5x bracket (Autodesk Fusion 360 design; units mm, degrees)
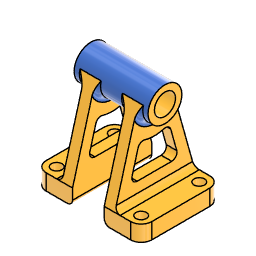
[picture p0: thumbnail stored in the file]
sketch "Sketch1" plane through (0, 0, 0) normal (1, 0, 0) x axis (0, 1, 0)
  line L1 (37.5, -75) -> (-37.5, -75)
  line L2 (37.5, -90) -> (37.5, -75)
  line L3 (-37.5, -90) -> (37.5, -90)
  line L4 (-37.5, -75) -> (-37.5, -90)
  line L5 (37.5, -90) -> (-37.5, -75)
  line L6 (-37.5, -90) -> (37.5, -75)
  line L7 (-15.4132, 4.2933) -> (-37.5, -75)
  line L8 (15.4132, 4.2933) -> (37.5, -75)
  circle C1 centre (0, 0) radius 10
  circle C2 centre (0, 0) radius 16
  point P1 (0, 0)
  point P2 (0, 0)
  point P8 (0, -82.5)
  point P3 (0, 0)
  point P9 (-15.4132, 4.2933)
  point P10 (15.4132, 4.2933)
  point P5 (37.5, -75)
  point P6 (37.5, -90)
  point P7 (-37.5, -90)
  coincident P1 P2
  concentric C1 C2
  horizontal L1
  perpendicular L1 L2
  parallel L1 L3
  parallel L2 L4
  coincident L5 P8
  coincident L6 P8
  vertical P3 P8
  coincident C2 P9
  tangent C2 L7
  coincident C2 P10
  tangent C2 L8
  dimension "d1" diameter C1 = 20
  dimension "d2" distance C1 C2 = 6
  dimension "d3" distance P5 P6 = 15
  dimension "d4" distance P6 P7 = 75
  dimension "d5" distance P3 L1 = 75
extrude "Extrude1" new body sketch "Sketch1" profile of C1 C2 L1 L2 L3 L4 L7 L8 distance 25
extrude "Extrude2" add sketch "Sketch1" profile of C1 C2 distance 35
extrude "Extrude3" add sketch "Sketch1" profile of L1 L2 L3 L4 distance 50
fillet "Fillet1" radius 10
sketch "Sketch2" plane through (0, -37.5, 0) normal (0, -1, 0) x axis (1, 0, 0)
  line L1 (-40, -90) -> (-40, -75)
  line L2 (40, -90) -> (-40, -90)
  line L3 (40, -75) -> (40, -90)
  line L4 (25, -75) -> (40, -75)
  line L5 (-25, -75) -> (25, -75)
  line L6 (-40, -75) -> (-25, -75)
  line L7 (35, 16) -> (35, -16)
  line L8 (-35, -16) -> (-35, 16)
  line L9 (25, 4.2933) -> (-25, 4.2933)
  line L10 (25, -16) -> (25, 4.2933)
  line L11 (-25, 4.2933) -> (25, 4.2933)
  line L12 (-25, 4.2933) -> (-25, -16)
  line L13 (-25, -75) -> (-25, -16)
  line L14 (25, -75) -> (25, -16)
  line L15 (15, -16) -> (-15, -16)
  line L16 (15, -75) -> (15, -16)
  line L17 (-15, -75) -> (15, -75)
  line L18 (-15, -16) -> (-15, -75)
  line L19 (-25, -90) -> (-25, -75)
  line L20 (25, -90) -> (25, -75)
  line L21 (-15, -90) -> (-15, -75)
  line L22 (15, -90) -> (15, -75)
  point P15 (-25, -16)
  point P16 (-25, -16)
  point P7 (-25, -75)
  point P17 (-25, -75)
  point P14 (25, -16)
  point P18 (25, -16)
  point P6 (25, -75)
  point P19 (25, -75)
  point P22 (15, -75)
  point P24 (-25, -90)
  point P25 (25, -90)
  point P26 (-15, -90)
  point P27 (15, -90)
  coincident P15 P16
  coincident P7 P17
  coincident P14 P18
  coincident P6 P19
  horizontal L15
  vertical L16
  horizontal L17
  vertical L18
  coincident L5 P22
  coincident P16 L15
  coincident L2 P24
  perpendicular L2 L19
  coincident L2 P25
  perpendicular L2 L20
  coincident L2 P26
  perpendicular L2 L21
  coincident L2 P27
  perpendicular L2 L22
  dimension "d14" distance L13 L18 = 10
  dimension "d15" distance L14 L16 = 10 (= "d14")
extrude "Extrude4" cut sketch "Sketch2" profile of L2 L5 L15 L16 L17 L18 L21 L22 no distance stored
sketch "Sketch3" plane through (0, 0, 0) normal (1, 0, 0) x axis (0, 1, 0)
  line L1 (37.5, -75) -> (-37.5, -75)
  line L2 (15.4132, 4.2933) -> (37.5, -75)
  line L3 (-37.5, -75) -> (-15.4132, 4.2933)
  circle C1 centre (0, 0) radius 26.4532
  arc A1 centre (0, 0) radius 16 clockwise from (15.4132, 4.2933) to (-15.4132, 4.2933)
  point P1 (0, 0)
  point P2 (0, 0)
  point P3 (21.0658, -16)
  coincident P1 P2
  coincident C1 P3
extrude "Extrude5" cut sketch "Sketch3" profile of C1 L2 A1 L3 to an object Side2Offset 0
fillet "Fillet2" radius 5
sketch "Sketch4" plane through (0, 0, -90) normal (0, 0, -1) x axis (1, 0, 0)
  line L1 (20, -37.5) -> (20, 37.5)
  line L2 (40, -37.5) -> (20, -37.5)
  line L3 (50, 27.5) -> (50, -27.5)
  line L4 (20, 37.5) -> (40, 37.5)
  line L5 (-20, 37.5) -> (-20, -37.5)
  line L6 (-40, 37.5) -> (-20, 37.5)
  line L7 (-50, -27.5) -> (-50, 27.5)
  line L8 (-20, -37.5) -> (-40, -37.5)
  arc A1 centre (40, -27.5) radius 10 clockwise from (50, -27.5) to (40, -37.5)
  arc A2 centre (40, 27.5) radius 10 clockwise from (40, 37.5) to (50, 27.5)
  arc A3 centre (-40, 27.5) radius 10 clockwise from (-50, 27.5) to (-40, 37.5)
  arc A4 centre (-40, -27.5) radius 10 clockwise from (-40, -37.5) to (-50, -27.5)
  circle C1 centre (40, 27.5) radius 5
  circle C2 centre (40, -27.5) radius 5
  circle C3 centre (-40, -27.5) radius 5
  circle C4 centre (-40, 27.5) radius 5
  concentric A2 C1
  concentric A1 C2
  concentric A4 C3
  concentric A3 C4
  equal C3 C4
  equal C2 C3
  equal C1 C2
  dimension "d23" diameter C1 = 10
extrude "Extrude6" cut sketch "Sketch4" profile of C1 C2 C3 C4 to an object
sketch "Sketch5" plane through (25, 0, 0) normal (1, 0, 0) x axis (0, 1, 0)
  line L1 (36.1073, -70) -> (-36.1073, -70)
  line L2 (19.0629, -8.8094) -> (36.1073, -70)
  line L3 (-36.1073, -70) -> (-19.0629, -8.8094)
  line L4 (13.9409, -27.6885) -> (22.9411, -60)
  line L5 (22.9411, -60) -> (-22.9411, -60)
  line L6 (-22.9411, -60) -> (-13.9409, -27.6885)
  arc A1 centre (0, 0) radius 21 clockwise from (19.0629, -8.8094) to (-19.0629, -8.8094)
  arc A2 centre (0, 0) radius 31 clockwise from (13.9409, -27.6885) to (-13.9409, -27.6885)
  dimension "d26" = -10
extrude "Extrude7" cut sketch "Sketch5" profile of L4 A2 L5 L6 no distance stored
fillet "Fillet3" radius 5
component_from_bodies "Body->Comp"
base_feature "Base Feature1"
base_feature "Base Feature1"
base_feature "Base Feature1"
base_feature "Base Feature1"
sketch "Sketch1" plane through (0, 0, 0) normal (1, 0, 0) x axis (0, 1, 0)
  line L1 (-7.5, 34.615) -> (-7.5, 19.615)
  line L2 (7.5, 34.615) -> (-7.5, 34.615)
  line L3 (7.5, 19.615) -> (7.5, 34.615)
  line L4 (-17.5, 34.615) -> (-7.5, 34.615)
  line L5 (-17.5, 44.615) -> (-17.5, 34.615)
  line L6 (17.5, 44.615) -> (-17.5, 44.615)
  line L7 (17.5, 34.615) -> (17.5, 44.615)
  line L8 (7.5, 34.615) -> (17.5, 34.615)
  circle C1 centre (0, 0) radius 16
  circle C2 centre (-7.5, 19.615) radius 5
  circle C3 centre (7.5, 19.615) radius 5
  point P3 (-7.5, 19.615)
  point P5 (-7.5, 19.615)
  point P4 (7.5, 19.615)
  point P8 (7.5, 19.615)
  point P1 (0, 0)
  point P7 (7.5, 34.615)
  point P11 (17.5, 44.615)
  point P12 (17.5, 34.615)
  equal C2 C3
  tangent C1 C3
  tangent C1 C2
  coincident P3 P5
  vertical L1
  perpendicular L1 L2
  coincident P4 P8
  perpendicular L2 L3
  perpendicular L1 L4
  perpendicular L4 L5
  perpendicular L5 L6
  perpendicular L4 L7
  perpendicular L7 L8
  equal L4 L8
  equal L4 L5
  dimension "d30" diameter C3 = 10
  dimension "d31" distance P3 P4 = 15
  dimension "d32" distance P1 P4 = 7.5 (= "d31 / 2")
  dimension "d33" distance P7 P8 = 15
  dimension "d34" distance P11 P12 = 10
extrude "Extrude1" add sketch "Sketch1" distance 1
sketch "Sketch1" plane through (0, 0, 0) normal (1, 0, 0) x axis (0, 1, 0)
  line L1 (19.0629, -8.8094) -> (36.1073, -70)
  line L2 (34.4943, -64.2094) -> (31.811, -54.5761)
  line L3 (49.1406, -60.1297) -> (34.4943, -64.2094)
  line L4 (46.4573, -50.4964) -> (49.1406, -60.1297)
  line L5 (31.811, -54.5761) -> (46.4573, -50.4964)
  line L6 (51.8239, -69.763) -> (43.774, -40.8632)
  line L7 (61.8239, -66.9775) -> (51.8239, -69.763)
  line L8 (53.774, -38.0777) -> (61.8239, -66.9775)
  line L9 (43.774, -40.8632) -> (53.774, -38.0777)
  circle C1 centre (35.6643, -53.5028) radius 4
  circle C2 centre (38.3476, -63.136) radius 4
  point P5 (34.4943, -64.2094)
  point P7 (46.4573, -50.4964)
  point P12 (35.6643, -53.5028)
  point P4 (31.811, -54.5761)
  point P13 (38.3476, -63.136)
  point P8 (43.774, -40.8632)
  point P11 (53.774, -38.0777)
  perpendicular L2 L3
  parallel L2 L4
  parallel L3 L5
  coincident L1 P5
  parallel L1 L2
  perpendicular L6 L7
  parallel L6 L8
  parallel L7 L9
  perpendicular L5 L6
  coincident P7 L6
  coincident L5 P12
  coincident P4 C1
  coincident L3 P13
  coincident P5 C2
  equal C1 C2
  dimension "d37" distance L3 L5 = 10
  dimension "d38" distance L5 L9 = 10
  dimension "d39" distance L3 L7 = 10 (= "d38")
  dimension "d40" distance P8 P11 = 10
  dimension "d56" diameter C1 = 8
extrude "Extrude1" sketch "Sketch1" blind -2.5
mirror "Mirror1" mirrorStitchTolerance 0.1
sketch "Sketch1" plane through (0, 0, 0) normal (0, 1, 0) x axis (1, 0, 0)
  line L1 (20, 90) -> (50, 90)
  line L2 (-50, 90) -> (-20, 90)
  line L3 (25, 104) -> (25, 94)
  line L4 (35, 104) -> (25, 104)
  line L5 (35, 94) -> (35, 104)
  line L6 (-25, 104) -> (-25, 94)
  line L7 (-35, 104) -> (-25, 104)
  line L8 (-35, 94) -> (-35, 104)
  line L9 (43.6078, 104) -> (35, 104)
  line L10 (43.6078, 118.3729) -> (43.6078, 104)
  line L11 (16.3922, 118.3729) -> (43.6078, 118.3729)
  line L12 (16.3922, 104) -> (16.3922, 118.3729)
  line L13 (25, 104) -> (16.3922, 104)
  line L14 (-16.3922, 104) -> (-25, 104)
  line L15 (-16.3922, 118.3729) -> (-16.3922, 104)
  line L16 (-43.6078, 118.3729) -> (-16.3922, 118.3729)
  line L17 (-43.6078, 104) -> (-43.6078, 118.3729)
  line L18 (-35, 104) -> (-43.6078, 104)
  circle C1 centre (35, 94) radius 4
  circle C2 centre (25, 94) radius 4
  circle C3 centre (-25, 94) radius 4
  circle C4 centre (-35, 94) radius 4
  point P7 (25, 94)
  point P10 (25, 94)
  point P6 (35, 94)
  point P13 (35, 94)
  point P8 (-25, 94)
  point P14 (-25, 94)
  point P9 (-35, 94)
  point P17 (-35, 94)
  point P4 (-20, 90)
  point P3 (20, 90)
  point P11 (25, 104)
  tangent L1 C1
  tangent L1 C2
  tangent L2 C4
  equal C3 C4
  equal C2 C3
  equal C1 C2
  tangent L2 C3
  coincident P7 P10
  vertical L3
  perpendicular L3 L4
  coincident P6 P13
  perpendicular L4 L5
  coincident P8 P14
  vertical L6
  perpendicular L6 L7
  coincident P9 P17
  perpendicular L7 L8
  collinear L4 L7
  perpendicular L5 L9
  perpendicular L9 L10
  perpendicular L10 L11
  perpendicular L11 L12
  perpendicular L3 L13
  perpendicular L6 L14
  perpendicular L7 L15
  perpendicular L15 L16
  perpendicular L16 L17
  perpendicular L8 L18
  equal L13 L14
  equal L9 L18
  equal L14 L18
  equal L12 L15
  dimension "d48" diameter C1 = 8
  dimension "d49" distance P6 P7 = 10
  dimension "d50" distance P8 P9 = 10
  dimension "d51" distance P4 P8 = 5
  dimension "d52" distance P3 P7 = 5
  dimension "d53" distance P10 P11 = 10
extrude "Extrude1" add sketch "Sketch1" distance 2
sketch "Sketch1" plane through (0, 0, -90) normal (0, 0, -1) x axis (1, 0, 0)
  line L1 (20, -37.5) -> (20, 37.5)
  line L2 (40, -37.5) -> (20, -37.5)
  line L3 (50, 27.5) -> (50, -27.5)
  line L4 (20, 37.5) -> (40, 37.5)
  line L5 (64, 5) -> (54, 5)
  line L6 (64, -5) -> (64, 5)
  line L7 (54, -5) -> (64, -5)
  line L8 (64, -15) -> (64, -5)
  line L9 (74, -15) -> (64, -15)
  line L10 (74, 15) -> (74, -15)
  line L11 (64, 15) -> (74, 15)
  line L12 (64, 5) -> (64, 15)
  circle C1 centre (40, 27.5) radius 5
  circle C2 centre (40, -27.5) radius 5
  arc A1 centre (40, -27.5) radius 10 clockwise from (50, -27.5) to (40, -37.5)
  arc A2 centre (40, 27.5) radius 10 clockwise from (40, 37.5) to (50, 27.5)
  circle C3 centre (54, 5) radius 4
  circle C4 centre (54, -5) radius 4
  point P10 (54, 5)
  point P12 (54, 5)
  point P11 (54, -5)
  point P15 (54, -5)
  point P1 (0, 0)
  point P13 (64, 5)
  point P19 (64, 15)
  tangent L3 C3
  tangent L3 C4
  equal C3 C4
  coincident P10 P12
  perpendicular L3 L5
  perpendicular L5 L6
  coincident P11 P15
  perpendicular L6 L7
  perpendicular L7 L8
  perpendicular L8 L9
  perpendicular L9 L10
  perpendicular L5 L12
  horizontal L11
  equal L8 L12
  equal L11 L12
  dimension "d57" diameter C3 = 8
  dimension "d58" distance P10 P11 = 10
  dimension "d59" distance P1 P11 = 5
  dimension "d60" distance P13 P19 = 10
  dimension "d61" distance P12 P13 = 10
extrude "Extrude1" add sketch "Sketch1" profile of L3 C3 C4 L5 L6 L7 L8 L9 L10 L11 L12 against normal blind 2
mirror "Mirror1" mirrorStitchTolerance 0.1
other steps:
base_feature "Base Feature1"
create_component "CreateComponent1"
remove_body "RemoveBody1"
create_component "CreateComponent2"
create_component "CreateComponent3"
create_component "CreateComponent4"
create_component "CreateComponent5"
